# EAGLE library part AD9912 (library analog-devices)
1 GSPS Direct Digital Synthesizer with 14-Bit DAC Source: http://www.analog.com/static/imported-files/data_sheets/AD9912.pdf
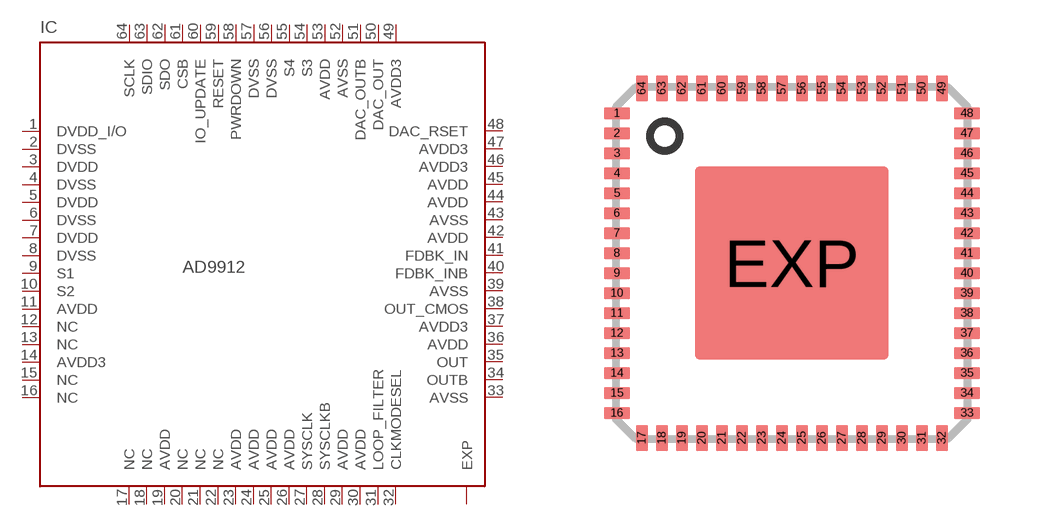
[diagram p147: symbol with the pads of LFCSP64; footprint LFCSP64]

Designator prefix IC

## AD9912 (MPN: AD9912BCPZ; OC_FARNELL: 1542712; OC_NEWARK: 61M3822)  [LFCSP64]
1  DVDD_I/O  pwr
2  DVSS  pwr
3  DVDD  pwr
4  DVSS  pwr
5  DVDD  pwr
6  DVSS  pwr
7  DVDD  pwr
8  DVSS  pwr
9  S1  in
10  S2  in
11  AVDD  pwr
12  NC  nc
13  NC  nc
14  AVDD3  pwr
15  NC  nc
16  NC  nc
17  NC  nc
18  NC  nc
19  AVDD  pwr
20  NC  nc
21  NC  nc
22  NC  nc
23  AVDD  pwr
24  AVDD  pwr
25  AVDD  pwr
26  AVDD  pwr
27  SYSCLK  in
28  SYSCLKB  in
29  AVDD  pwr
30  AVDD  pwr
31  LOOP_FILTER  in
32  CLKMODESEL  in
33  AVSS  pwr
34  OUTB  out
35  OUT  out
36  AVDD  pwr
37  AVDD3  pwr
38  OUT_CMOS  out
39  AVSS  pwr
40  FDBK_INB  in
41  FDBK_IN  in
42  AVDD  pwr
43  AVSS  pwr
44  AVDD  pwr
45  AVDD  pwr
46  AVDD3  pwr
47  AVDD3  pwr
48  DAC_RSET  in
49  AVDD3  pwr
50  DAC_OUT  out
51  DAC_OUTB  out
52  AVSS  pwr
53  AVDD  pwr
54  S3  in
55  S4  in
56  DVSS  pwr
57  DVSS  pwr
58  PWRDOWN  in
59  RESET  in
60  IO_UPDATE  in
61  CSB  in
62  SDO  in
63  SDIO  in
64  SCLK  in
EXP  EXP  pas

## Footprint LFCSP64 (pad centres in mm)
64-Lead Lead Frame Chip Scale Package [LFCSP] CP-64-1 9 x 9 mm Body Source: http://www.analog.com/UploadedFiles/Packages/40887351787287CP_64_1.pdf
smd 0.65 x 0.3: 1 -4.375,3.75; 2 -4.375,3.25; 3 -4.375,2.75; 4 -4.375,2.25; 5 -4.375,1.75; 6 -4.375,1.25; 7 -4.375,0.75; 8 -4.375,0.25; 9 -4.375,-0.25; 10 -4.375,-0.75; 11 -4.375,-1.25; 12 -4.375,-1.75; 13 -4.375,-2.25; 14 -4.375,-2.75; 15 -4.375,-3.25; 16 -4.375,-3.75; 33 4.375,-3.75; 34 4.375,-3.25; 35 4.375,-2.75; 36 4.375,-2.25; 37 4.375,-1.75; 38 4.375,-1.25; 39 4.375,-0.75; 40 4.375,-0.25; 41 4.375,0.25; 42 4.375,0.75; 43 4.375,1.25; 44 4.375,1.75; 45 4.375,2.25; 46 4.375,2.75; 47 4.375,3.25; 48 4.375,3.75
smd 0.3 x 0.65: 17 -3.75,-4.375; 18 -3.25,-4.375; 19 -2.75,-4.375; 20 -2.25,-4.375; 21 -1.75,-4.375; 22 -1.25,-4.375; 23 -0.75,-4.375; 24 -0.25,-4.375; 25 0.25,-4.375; 26 0.75,-4.375; 27 1.25,-4.375; 28 1.75,-4.375; 29 2.25,-4.375; 30 2.75,-4.375; 31 3.25,-4.375; 32 3.75,-4.375; 49 3.75,4.375; 50 3.25,4.375; 51 2.75,4.375; 52 2.25,4.375; 53 1.75,4.375; 54 1.25,4.375; 55 0.75,4.375; 56 0.25,4.375; 57 -0.25,4.375; 58 -0.75,4.375; 59 -1.25,4.375; 60 -1.75,4.375; 61 -2.25,4.375; 62 -2.75,4.375; 63 -3.25,4.375; 64 -3.75,4.375
smd 4.85 x 4.85: EXP 0,0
